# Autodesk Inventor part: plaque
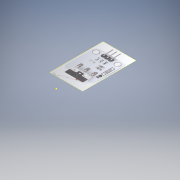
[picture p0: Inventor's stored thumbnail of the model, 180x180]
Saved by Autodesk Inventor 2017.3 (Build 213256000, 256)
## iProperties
Part Number: plaque
Material: Générique
Document SubType Name: Modeling
Designer: ficho
Density: 1 g/cm^3
Appearance: Par défaut
Author: ficho
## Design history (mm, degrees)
sketch "Esquisse1"
  geometry: L1 (-9.292, 6.243)-(-9.292, 43.554); L2 (-9.292, 43.554)-(-32.292, 43.554); L3 (-32.292, 43.554)-(-32.292, 6.243); L4 (-32.292, 6.243)-(-9.292, 6.243); L5 (-10.247, 16.224)-(-10.247, 35.553); L6 (-12.247, 37.553)-(-29.207, 37.553); L7 (-31.207, 35.553)-(-31.207, 16.224); L8 (-13.643, 14.224)-(-13.643, 16.514); L9 (-15.643, 18.514)-(-25.855, 18.514); L10 (-27.855, 16.514)-(-27.855, 14.224); L11 (-29.207, 14.224)-(-27.855, 14.224); L12 (-13.643, 14.224)-(-12.247, 14.224); C1 r 1.75 at (-28.436, 34.738); C2 r 1.75 at (-13.241, 34.738); A1 r 2 centre (-29.207, 16.224) between (-31.207, 16.224) and (-29.207, 14.224); A2 r 2 centre (-29.207, 35.553) between (-29.207, 37.553) and (-31.207, 35.553); A3 r 2 centre (-12.247, 35.553) between (-10.247, 35.553) and (-12.247, 37.553); A4 r 2 centre (-12.247, 16.224) between (-12.247, 14.224) and (-10.247, 16.224); A5 r 2 centre (-25.855, 16.514) between (-25.855, 18.514) and (-27.855, 16.514); A6 r 2 centre (-15.643, 16.514) between (-13.643, 16.514) and (-15.643, 18.514); 1 further point; 1 other entity
  constraints: 16 end point, 14 tangent, 12 point on circle, 8 centre point, 4 equal radius, 4 parallel, 2 horizontal, 2 perpendicular, 2 other
  dimensions: "d17" = 23 distance between parallel lines of L1 L3; "d31" = 2 radius of A1 (derived); "d32" = 2 radius of A5 (derived); "d33" = 3.5 diameter of C1; "d34" = 3.5 diameter of C2
  node "Image1"
node "Plan de construction1"
extrude "Extrusion1" new body sketch "Esquisse1" stored distance "d37" = 1.5; taper "d38" = 0 deg
sketch "Esquisse2"
  geometry: L1 (0, 23.834)-(1.1, 23.834); L2 (1.1, 23.834)-(1.1, -12.841); L3 (1.1, -12.841)-(0, -12.841); L4 (0, -12.841)-(0, 23.834); 1 further point
  constraints: 8 end point, 2 parallel, 1 horizontal, 1 perpendicular
  dimensions: "d39" = 1.1 distance of L2.end L3.end
extrude "Extrusion2" cut sketch "Esquisse2" stored distance "d40" = 10; taper "d41" = 0 deg
sketch "Esquisse3"
  geometry: L1 (-2.762, -31.215)-(-2.762, 6.097); L2 (-2.762, 6.097)-(20.238, 6.097); L3 (20.238, 6.097)-(20.238, -31.215); L4 (20.238, -31.215)-(-2.762, -31.215); 1 further point; 1 other entity
  constraints: 2 other
  dimensions: "d44" = 23 distance between parallel lines of L1 L3
feature "Décalcomanie1" sketch "Esquisse3"
node "Solide1"
node "Image2"
